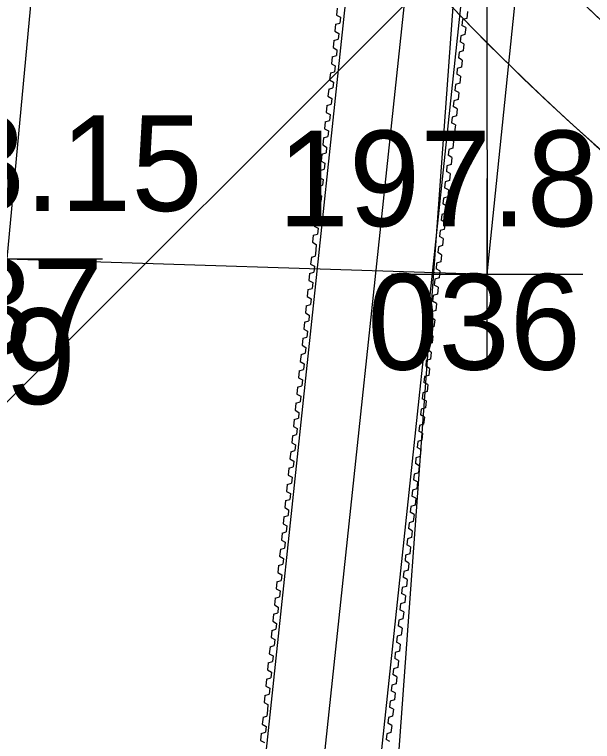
# Model space of a CAD drawing. Extents: x -706655 to -706193, y -1036183 to -1034979.
# Drawn here: x -706606.149 to -706603.13, y -1035105.504 to -1035101.703 of the extents above; entities that cross this region are included whole.
import ezdxf

# ---------------------------------------------------------------- set-up
doc = ezdxf.new("R2010")
doc.units = 0
for name, color, linetype in [('01', 7, 'Continuous'), ('křížky', 7, 'Continuous'), ('Nová vrstva (1)', 7, 'Continuous'), ('Nová vrstva (11)', 7, 'Continuous'), ('Nová vrstva (4)', 7, 'Continuous'), ('Stávající terén', 7, 'Continuous'), ('výšky', 7, 'Continuous'), ('čísla bodu', 7, 'Continuous')]:
    doc.layers.add(name, color=color, linetype=linetype)

msp = doc.modelspace()

# ---------------------------------------------------------------- linework, layer by layer
at = {"layer": '01'}
for p, q in [((-706604.0546, -1035098.1893), (-706605.8115, -1035114.7563)), ((-706603.4625, -1035098.2947), (-706605.2148, -1035114.8196)), ((-706604.4629, -1035101.6693), (-706604.4668, -1035101.7058)), ((-706604.4668, -1035101.7058), (-706604.4466, -1035101.717)), ((-706603.7829, -1035101.6865), (-706603.7868, -1035101.723)), ((-706604.4466, -1035101.717), (-706604.4498, -1035101.7474)), ((-706603.8088, -1035101.7298), (-706603.8121, -1035101.7601)), ((-706603.7868, -1035101.723), (-706603.8088, -1035101.7298)), ((-706604.4719, -1035101.7541), (-706604.4758, -1035101.7907)), ((-706604.4719, -1035101.7541), (-706604.4498, -1035101.7474)), ((-706603.7919, -1035101.7713), (-706603.8121, -1035101.7601)), ((-706603.7919, -1035101.7713), (-706603.7958, -1035101.8079)), ((-706604.4758, -1035101.7907), (-706604.4556, -1035101.8019)), ((-706604.4556, -1035101.8019), (-706604.4588, -1035101.8322)), ((-706603.8178, -1035101.8146), (-706603.8211, -1035101.845)), ((-706603.7958, -1035101.8079), (-706603.8178, -1035101.8146)), ((-706604.4809, -1035101.839), (-706604.4848, -1035101.8755)), ((-706604.4809, -1035101.839), (-706604.4588, -1035101.8322)), ((-706603.8009, -1035101.8562), (-706603.8211, -1035101.845)), ((-706603.8009, -1035101.8562), (-706603.8048, -1035101.8927)), ((-706604.4848, -1035101.8755), (-706604.4646, -1035101.8868)), ((-706604.4646, -1035101.8868), (-706604.4678, -1035101.9171)), ((-706603.8048, -1035101.8927), (-706603.8268, -1035101.8995)), ((-706604.4899, -1035101.9239), (-706604.4938, -1035101.9604)), ((-706604.4899, -1035101.9239), (-706604.4678, -1035101.9171)), ((-706603.8268, -1035101.8995), (-706603.8301, -1035101.9298)), ((-706603.8099, -1035101.9411), (-706603.8301, -1035101.9298)), ((-706604.4938, -1035101.9604), (-706604.4736, -1035101.9716)), ((-706604.4736, -1035101.9716), (-706604.4768, -1035102.002)), ((-706603.8099, -1035101.9411), (-706603.8138, -1035101.9776)), ((-706604.4989, -1035102.0087), (-706604.5028, -1035102.0453)), ((-706604.4989, -1035102.0087), (-706604.4768, -1035102.002)), ((-706603.8358, -1035101.9844), (-706603.8391, -1035102.0147)), ((-706603.8138, -1035101.9776), (-706603.8358, -1035101.9844)), ((-706604.5028, -1035102.0453), (-706604.4826, -1035102.0565)), ((-706603.8189, -1035102.0259), (-706603.8391, -1035102.0147)), ((-706603.8189, -1035102.0259), (-706603.8228, -1035102.0625)), ((-706604.5079, -1035102.0936), (-706604.4858, -1035102.0869)), ((-706604.4826, -1035102.0565), (-706604.4858, -1035102.0869)), ((-706603.8448, -1035102.0692), (-706603.8481, -1035102.0996)), ((-706603.8228, -1035102.0625), (-706603.8448, -1035102.0692)), ((-706604.5079, -1035102.0936), (-706604.5118, -1035102.1301)), ((-706603.8279, -1035102.1108), (-706603.8481, -1035102.0996)), ((-706603.8279, -1035102.1108), (-706603.8318, -1035102.1473)), ((-706604.5118, -1035102.1301), (-706604.4916, -1035102.1414)), ((-706604.4916, -1035102.1414), (-706604.4948, -1035102.1717)), ((-706603.8538, -1035102.1541), (-706603.8571, -1035102.1844)), ((-706603.8318, -1035102.1473), (-706603.8538, -1035102.1541)), ((-706604.5169, -1035102.1785), (-706604.5208, -1035102.215)), ((-706604.5169, -1035102.1785), (-706604.4948, -1035102.1717)), ((-706603.8369, -1035102.1957), (-706603.8571, -1035102.1844)), ((-706603.8369, -1035102.1957), (-706603.8408, -1035102.2322)), ((-706604.5208, -1035102.215), (-706604.5006, -1035102.2262)), ((-706604.5006, -1035102.2262), (-706604.5038, -1035102.2566)), ((-706603.8628, -1035102.239), (-706603.8661, -1035102.2693)), ((-706603.8408, -1035102.2322), (-706603.8628, -1035102.239)), ((-706604.5259, -1035102.2633), (-706604.5298, -1035102.2999)), ((-706604.5259, -1035102.2633), (-706604.5038, -1035102.2566)), ((-706603.8459, -1035102.2805), (-706603.8661, -1035102.2693)), ((-706604.5298, -1035102.2999), (-706604.5096, -1035102.3111)), ((-706604.5096, -1035102.3111), (-706604.5128, -1035102.3415)), ((-706603.8498, -1035102.3171), (-706603.8718, -1035102.3238)), ((-706603.8459, -1035102.2805), (-706603.8498, -1035102.3171)), ((-706604.5349, -1035102.3482), (-706604.5388, -1035102.3847)), ((-706604.5349, -1035102.3482), (-706604.5128, -1035102.3415)), ((-706603.8718, -1035102.3238), (-706603.8751, -1035102.3542)), ((-706603.8549, -1035102.3654), (-706603.8751, -1035102.3542)), ((-706604.5388, -1035102.3847), (-706604.5186, -1035102.396)), ((-706603.8549, -1035102.3654), (-706603.8588, -1035102.4019)), ((-706604.5439, -1035102.4331), (-706604.5218, -1035102.4263)), ((-706604.5186, -1035102.396), (-706604.5218, -1035102.4263)), ((-706603.8808, -1035102.4087), (-706603.8841, -1035102.439)), ((-706603.8588, -1035102.4019), (-706603.8808, -1035102.4087)), ((-706604.5439, -1035102.4331), (-706604.5478, -1035102.4696)), ((-706603.8639, -1035102.4503), (-706603.8841, -1035102.439)), ((-706603.8639, -1035102.4503), (-706603.8678, -1035102.4868)), ((-706604.5478, -1035102.4696), (-706604.5276, -1035102.4808)), ((-706604.5276, -1035102.4808), (-706604.5308, -1035102.5112)), ((-706603.8898, -1035102.4936), (-706603.8931, -1035102.5239)), ((-706603.8678, -1035102.4868), (-706603.8898, -1035102.4936)), ((-706604.5529, -1035102.5179), (-706604.5568, -1035102.5545)), ((-706604.5529, -1035102.5179), (-706604.5308, -1035102.5112)), ((-706603.8729, -1035102.5351), (-706603.8931, -1035102.5239)), ((-706603.8729, -1035102.5351), (-706603.8768, -1035102.5717)), ((-706604.5568, -1035102.5545), (-706604.5366, -1035102.5657)), ((-706604.5366, -1035102.5657), (-706604.5398, -1035102.5961)), ((-706603.8988, -1035102.5784), (-706603.9021, -1035102.6088)), ((-706603.8768, -1035102.5717), (-706603.8988, -1035102.5784)), ((-706604.5619, -1035102.6028), (-706604.5658, -1035102.6393)), ((-706604.5619, -1035102.6028), (-706604.5398, -1035102.5961)), ((-706603.8819, -1035102.62), (-706603.9021, -1035102.6088)), ((-706603.8819, -1035102.62), (-706603.8858, -1035102.6565)), ((-706604.5658, -1035102.6393), (-706604.5456, -1035102.6506)), ((-706604.5456, -1035102.6506), (-706604.5488, -1035102.6809)), ((-706603.8858, -1035102.6565), (-706603.9078, -1035102.6633)), ((-706604.5709, -1035102.6877), (-706604.5748, -1035102.7242)), ((-706604.5709, -1035102.6877), (-706604.5488, -1035102.6809)), ((-706603.9078, -1035102.6633), (-706603.9111, -1035102.6936)), ((-706603.8909, -1035102.7049), (-706603.9111, -1035102.6936)), ((-706604.5748, -1035102.7242), (-706604.5546, -1035102.7354)), ((-706604.5546, -1035102.7354), (-706604.5578, -1035102.7658)), ((-706603.8909, -1035102.7049), (-706603.8948, -1035102.7414)), ((-706604.5799, -1035102.7725), (-706604.5838, -1035102.8091)), ((-706604.5799, -1035102.7725), (-706604.5578, -1035102.7658)), ((-706603.9168, -1035102.7482), (-706603.9201, -1035102.7785)), ((-706603.8948, -1035102.7414), (-706603.9168, -1035102.7482)), ((-706604.5838, -1035102.8091), (-706604.5636, -1035102.8203)), ((-706603.8999, -1035102.7897), (-706603.9201, -1035102.7785)), ((-706603.8999, -1035102.7897), (-706603.9038, -1035102.8263)), ((-706604.5636, -1035102.8203), (-706604.5668, -1035102.8507)), ((-706603.9258, -1035102.833), (-706603.9291, -1035102.8634)), ((-706603.9038, -1035102.8263), (-706603.9258, -1035102.833)), ((-706604.5889, -1035102.8574), (-706604.5928, -1035102.8939)), ((-706604.5889, -1035102.8574), (-706604.5668, -1035102.8507)), ((-706603.9089, -1035102.8746), (-706603.9291, -1035102.8634)), ((-706603.9089, -1035102.8746), (-706603.9128, -1035102.9111)), ((-706604.5928, -1035102.8939), (-706604.5726, -1035102.9052)), ((-706604.5726, -1035102.9052), (-706604.5758, -1035102.9355)), ((-706603.9348, -1035102.9179), (-706603.9381, -1035102.9482)), ((-706603.9128, -1035102.9111), (-706603.9348, -1035102.9179)), ((-706604.5758, -1035102.9355), (-706604.579, -1035102.9659)), ((-706603.9179, -1035102.9595), (-706603.9381, -1035102.9482)), ((-706603.9179, -1035102.9595), (-706603.9218, -1035102.996)), ((-706604.5984, -1035102.9718), (-706604.6023, -1035103.0083)), ((-706604.5984, -1035102.9718), (-706604.579, -1035102.9659)), ((-706603.9218, -1035102.9958), (-706603.9438, -1035103.0025)), ((-706603.9218, -1035102.996), (-706603.9438, -1035103.0028)), ((-706604.6023, -1035103.0083), (-706604.5822, -1035103.0196)), ((-706604.5822, -1035103.0196), (-706604.5854, -1035103.0499)), ((-706603.9438, -1035103.0025), (-706603.947, -1035103.0329)), ((-706603.9269, -1035103.0441), (-706603.947, -1035103.0329)), ((-706604.6074, -1035103.0567), (-706604.6113, -1035103.0932)), ((-706604.6074, -1035103.0567), (-706604.5854, -1035103.0499)), ((-706603.9269, -1035103.0441), (-706603.9308, -1035103.0807)), ((-706604.6113, -1035103.0932), (-706604.5912, -1035103.1044)), ((-706604.5912, -1035103.1044), (-706604.5944, -1035103.1348)), ((-706603.9528, -1035103.0874), (-706603.956, -1035103.1178)), ((-706603.9308, -1035103.0807), (-706603.9528, -1035103.0874)), ((-706604.6164, -1035103.1415), (-706604.6203, -1035103.1781)), ((-706604.6164, -1035103.1415), (-706604.5944, -1035103.1348)), ((-706603.9359, -1035103.129), (-706603.956, -1035103.1178)), ((-706603.9359, -1035103.129), (-706603.9398, -1035103.1655)), ((-706604.6203, -1035103.1781), (-706604.6002, -1035103.1893)), ((-706604.6002, -1035103.1893), (-706604.6034, -1035103.2197)), ((-706603.9618, -1035103.1723), (-706603.965, -1035103.2026)), ((-706603.9398, -1035103.1655), (-706603.9618, -1035103.1723)), ((-706604.6254, -1035103.2264), (-706604.6293, -1035103.2629)), ((-706604.6254, -1035103.2264), (-706604.6034, -1035103.2197)), ((-706603.9449, -1035103.2139), (-706603.965, -1035103.2026)), ((-706603.9449, -1035103.2139), (-706603.9488, -1035103.2504)), ((-706604.6293, -1035103.2629), (-706604.6092, -1035103.2742)), ((-706603.9708, -1035103.2571), (-706603.974, -1035103.2875)), ((-706603.9488, -1035103.2504), (-706603.9708, -1035103.2571)), ((-706604.6344, -1035103.3113), (-706604.6124, -1035103.3045)), ((-706604.6092, -1035103.2742), (-706604.6124, -1035103.3045)), ((-706603.9539, -1035103.2987), (-706603.974, -1035103.2875)), ((-706603.9539, -1035103.2987), (-706603.9578, -1035103.3353)), ((-706604.6344, -1035103.3113), (-706604.6383, -1035103.3478)), ((-706603.9798, -1035103.342), (-706603.983, -1035103.3724)), ((-706603.9578, -1035103.3353), (-706603.9798, -1035103.342)), ((-706604.6383, -1035103.3478), (-706604.6182, -1035103.359)), ((-706604.6182, -1035103.359), (-706604.6214, -1035103.3894)), ((-706603.9629, -1035103.3836), (-706603.983, -1035103.3724)), ((-706604.6434, -1035103.3961), (-706604.6473, -1035103.4327)), ((-706604.6434, -1035103.3961), (-706604.6214, -1035103.3894)), ((-706603.9629, -1035103.3836), (-706603.9668, -1035103.4201)), ((-706604.6473, -1035103.4327), (-706604.6272, -1035103.4439)), ((-706604.6272, -1035103.4439), (-706604.6304, -1035103.4743)), ((-706603.9888, -1035103.4269), (-706603.992, -1035103.4572)), ((-706603.9719, -1035103.4685), (-706603.992, -1035103.4572)), ((-706603.9668, -1035103.4201), (-706603.9888, -1035103.4269)), ((-706604.6524, -1035103.481), (-706604.6563, -1035103.5175)), ((-706604.6524, -1035103.481), (-706604.6304, -1035103.4743)), ((-706603.9719, -1035103.4685), (-706603.9758, -1035103.505)), ((-706604.6563, -1035103.5175), (-706604.6362, -1035103.5288)), ((-706604.6362, -1035103.5288), (-706604.6394, -1035103.5591)), ((-706603.9978, -1035103.5117), (-706604.001, -1035103.5421)), ((-706603.9758, -1035103.505), (-706603.9978, -1035103.5117)), ((-706604.6614, -1035103.5659), (-706604.6653, -1035103.6024)), ((-706604.6614, -1035103.5659), (-706604.6394, -1035103.5591)), ((-706603.9809, -1035103.5533), (-706604.001, -1035103.5421)), ((-706603.9809, -1035103.5533), (-706603.9848, -1035103.5899)), ((-706604.6653, -1035103.6024), (-706604.6452, -1035103.6136)), ((-706604.0068, -1035103.5966), (-706604.01, -1035103.627)), ((-706603.9848, -1035103.5899), (-706604.0068, -1035103.5966)), ((-706604.6704, -1035103.6507), (-706604.6484, -1035103.644)), ((-706604.6452, -1035103.6136), (-706604.6484, -1035103.644)), ((-706603.9899, -1035103.6382), (-706604.01, -1035103.627)), ((-706603.9899, -1035103.6382), (-706603.9938, -1035103.6747)), ((-706604.6704, -1035103.6507), (-706604.6743, -1035103.6873)), ((-706604.0158, -1035103.6815), (-706604.019, -1035103.7118)), ((-706603.9938, -1035103.6747), (-706604.0158, -1035103.6815)), ((-706604.6743, -1035103.6873), (-706604.6542, -1035103.6985)), ((-706604.6542, -1035103.6985), (-706604.6574, -1035103.7289)), ((-706603.9989, -1035103.7231), (-706604.019, -1035103.7118)), ((-706603.9989, -1035103.7231), (-706604.0028, -1035103.7596)), ((-706604.6794, -1035103.7356), (-706604.6833, -1035103.7721)), ((-706604.6794, -1035103.7356), (-706604.6574, -1035103.7289)), ((-706604.0028, -1035103.7596), (-706604.0248, -1035103.7663)), ((-706604.6833, -1035103.7721), (-706604.6632, -1035103.7834)), ((-706604.6632, -1035103.7834), (-706604.6664, -1035103.8137)), ((-706604.0248, -1035103.7663), (-706604.028, -1035103.7967)), ((-706604.0079, -1035103.8079), (-706604.028, -1035103.7967)), ((-706604.6884, -1035103.8205), (-706604.6923, -1035103.857)), ((-706604.6884, -1035103.8205), (-706604.6664, -1035103.8137)), ((-706604.0079, -1035103.8079), (-706604.0118, -1035103.8445)), ((-706604.6923, -1035103.857), (-706604.6722, -1035103.8682)), ((-706604.6722, -1035103.8682), (-706604.6754, -1035103.8986)), ((-706604.0338, -1035103.8512), (-706604.037, -1035103.8816)), ((-706604.0118, -1035103.8445), (-706604.0338, -1035103.8512)), ((-706604.6974, -1035103.9053), (-706604.7013, -1035103.9419)), ((-706604.6974, -1035103.9053), (-706604.6754, -1035103.8986)), ((-706604.0169, -1035103.8928), (-706604.037, -1035103.8816)), ((-706604.0169, -1035103.8928), (-706604.0208, -1035103.9293)), ((-706604.7013, -1035103.9419), (-706604.6812, -1035103.9531)), ((-706604.0428, -1035103.9361), (-706604.046, -1035103.9664)), ((-706604.0208, -1035103.9293), (-706604.0428, -1035103.9361)), ((-706604.7064, -1035103.9902), (-706604.6844, -1035103.9835)), ((-706604.6812, -1035103.9531), (-706604.6844, -1035103.9835)), ((-706604.0259, -1035103.9777), (-706604.046, -1035103.9664)), ((-706604.0259, -1035103.9777), (-706604.0298, -1035104.0142)), ((-706604.7064, -1035103.9902), (-706604.7103, -1035104.0267)), ((-706604.7103, -1035104.0267), (-706604.6902, -1035104.038)), ((-706604.0518, -1035104.0209), (-706604.055, -1035104.0513)), ((-706604.0298, -1035104.0142), (-706604.0518, -1035104.0209)), ((-706604.6902, -1035104.038), (-706604.6934, -1035104.0683)), ((-706604.0349, -1035104.0625), (-706604.055, -1035104.0513)), ((-706604.0349, -1035104.0625), (-706604.0388, -1035104.0991)), ((-706604.7154, -1035104.0751), (-706604.7193, -1035104.1116)), ((-706604.7154, -1035104.0751), (-706604.6934, -1035104.0683)), ((-706604.0388, -1035104.0991), (-706604.0608, -1035104.1058)), ((-706604.7193, -1035104.1116), (-706604.6992, -1035104.1228)), ((-706604.6992, -1035104.1228), (-706604.7024, -1035104.1532)), ((-706604.0608, -1035104.1058), (-706604.064, -1035104.1362)), ((-706604.0439, -1035104.1474), (-706604.064, -1035104.1362)), ((-706604.7244, -1035104.1599), (-706604.7283, -1035104.1965)), ((-706604.7244, -1035104.1599), (-706604.7024, -1035104.1532)), ((-706604.0439, -1035104.1474), (-706604.0478, -1035104.1839)), ((-706604.7283, -1035104.1965), (-706604.7082, -1035104.2077)), ((-706604.7082, -1035104.2077), (-706604.7114, -1035104.2381)), ((-706604.0698, -1035104.1907), (-706604.073, -1035104.221)), ((-706604.0478, -1035104.1839), (-706604.0698, -1035104.1907)), ((-706604.7334, -1035104.2448), (-706604.7373, -1035104.2813)), ((-706604.7334, -1035104.2448), (-706604.7114, -1035104.2381)), ((-706604.0529, -1035104.2323), (-706604.073, -1035104.221)), ((-706604.0529, -1035104.2323), (-706604.0568, -1035104.2688)), ((-706604.7373, -1035104.2813), (-706604.7172, -1035104.2926)), ((-706604.7172, -1035104.2926), (-706604.7204, -1035104.3229)), ((-706604.0788, -1035104.2755), (-706604.082, -1035104.3059)), ((-706604.0568, -1035104.2688), (-706604.0788, -1035104.2755)), ((-706604.7424, -1035104.3297), (-706604.7463, -1035104.3662)), ((-706604.7424, -1035104.3297), (-706604.7204, -1035104.3229)), ((-706604.0619, -1035104.3171), (-706604.082, -1035104.3059)), ((-706604.0619, -1035104.3171), (-706604.0658, -1035104.3537)), ((-706604.7463, -1035104.3662), (-706604.7262, -1035104.3774)), ((-706604.0878, -1035104.3604), (-706604.091, -1035104.3908)), ((-706604.0658, -1035104.3537), (-706604.0878, -1035104.3604)), ((-706604.7514, -1035104.4145), (-706604.7294, -1035104.4078)), ((-706604.7262, -1035104.3774), (-706604.7294, -1035104.4078)), ((-706604.0709, -1035104.402), (-706604.091, -1035104.3908)), ((-706604.0709, -1035104.402), (-706604.0747, -1035104.4385)), ((-706604.7514, -1035104.4145), (-706604.7553, -1035104.4511)), ((-706604.0968, -1035104.4453), (-706604.1, -1035104.4756)), ((-706604.0747, -1035104.4385), (-706604.0968, -1035104.4453)), ((-706604.7553, -1035104.4511), (-706604.7352, -1035104.4623)), ((-706604.7352, -1035104.4623), (-706604.7384, -1035104.4927)), ((-706604.0799, -1035104.4869), (-706604.1, -1035104.4756)), ((-706604.7604, -1035104.4994), (-706604.7643, -1035104.5359)), ((-706604.7604, -1035104.4994), (-706604.7384, -1035104.4927)), ((-706604.0799, -1035104.4869), (-706604.0837, -1035104.5234)), ((-706604.7643, -1035104.5359), (-706604.7442, -1035104.5472)), ((-706604.7442, -1035104.5472), (-706604.7474, -1035104.5775)), ((-706604.1058, -1035104.5301), (-706604.109, -1035104.5605)), ((-706604.0837, -1035104.5234), (-706604.1058, -1035104.5301)), ((-706604.7694, -1035104.5843), (-706604.7733, -1035104.6208)), ((-706604.7694, -1035104.5843), (-706604.7474, -1035104.5775)), ((-706604.0889, -1035104.5717), (-706604.109, -1035104.5605)), ((-706604.0889, -1035104.5717), (-706604.0927, -1035104.6083)), ((-706604.7733, -1035104.6208), (-706604.7532, -1035104.632)), ((-706604.7532, -1035104.632), (-706604.7564, -1035104.6624)), ((-706604.1148, -1035104.615), (-706604.118, -1035104.6454)), ((-706604.0927, -1035104.6083), (-706604.1148, -1035104.615)), ((-706604.7784, -1035104.6691), (-706604.7823, -1035104.7057)), ((-706604.7784, -1035104.6691), (-706604.7564, -1035104.6624)), ((-706604.0979, -1035104.6566), (-706604.118, -1035104.6454)), ((-706604.0979, -1035104.6566), (-706604.1017, -1035104.6931)), ((-706604.7823, -1035104.7057), (-706604.7622, -1035104.7169)), ((-706604.1238, -1035104.6999), (-706604.127, -1035104.7302)), ((-706604.1017, -1035104.6931), (-706604.1238, -1035104.6999)), ((-706604.7874, -1035104.754), (-706604.7654, -1035104.7473)), ((-706604.7622, -1035104.7169), (-706604.7654, -1035104.7473)), ((-706604.1069, -1035104.7415), (-706604.127, -1035104.7302)), ((-706604.1069, -1035104.7415), (-706604.1107, -1035104.778)), ((-706604.7874, -1035104.754), (-706604.7913, -1035104.7905)), ((-706604.1328, -1035104.7847), (-706604.136, -1035104.8151)), ((-706604.1107, -1035104.778), (-706604.1328, -1035104.7847)), ((-706604.7913, -1035104.7905), (-706604.7712, -1035104.8018)), ((-706604.7712, -1035104.8018), (-706604.7744, -1035104.8321)), ((-706604.1159, -1035104.8263), (-706604.136, -1035104.8151)), ((-706604.7964, -1035104.8389), (-706604.8003, -1035104.8754)), ((-706604.7964, -1035104.8389), (-706604.7744, -1035104.8321)), ((-706604.1197, -1035104.8627), (-706604.1418, -1035104.8694)), ((-706604.1197, -1035104.8629), (-706604.1418, -1035104.8696)), ((-706604.1159, -1035104.8263), (-706604.1197, -1035104.8629)), ((-706604.8003, -1035104.8754), (-706604.7802, -1035104.8866)), ((-706604.7802, -1035104.8866), (-706604.7834, -1035104.917)), ((-706604.1418, -1035104.8694), (-706604.145, -1035104.8998)), ((-706604.1248, -1035104.911), (-706604.145, -1035104.8998)), ((-706604.8054, -1035104.9237), (-706604.8093, -1035104.9603)), ((-706604.8054, -1035104.9237), (-706604.7834, -1035104.917)), ((-706604.1248, -1035104.911), (-706604.1287, -1035104.9475)), ((-706604.8093, -1035104.9603), (-706604.7892, -1035104.9715)), ((-706604.7892, -1035104.9715), (-706604.7924, -1035105.0019)), ((-706604.1508, -1035104.9543), (-706604.154, -1035104.9846)), ((-706604.1287, -1035104.9475), (-706604.1508, -1035104.9543)), ((-706604.8144, -1035105.0086), (-706604.8183, -1035105.0451)), ((-706604.8144, -1035105.0086), (-706604.7924, -1035105.0019)), ((-706604.1338, -1035104.9959), (-706604.154, -1035104.9846)), ((-706604.1338, -1035104.9959), (-706604.1377, -1035105.0324)), ((-706604.8183, -1035105.0451), (-706604.7982, -1035105.0564)), ((-706604.1598, -1035105.0391), (-706604.163, -1035105.0695)), ((-706604.1377, -1035105.0324), (-706604.1598, -1035105.0391)), ((-706604.8234, -1035105.0935), (-706604.8014, -1035105.0867)), ((-706604.7982, -1035105.0564), (-706604.8014, -1035105.0867)), ((-706604.1428, -1035105.0807), (-706604.163, -1035105.0695)), ((-706604.1428, -1035105.0807), (-706604.1467, -1035105.1173)), ((-706604.8234, -1035105.0935), (-706604.8273, -1035105.13)), ((-706604.8273, -1035105.13), (-706604.8072, -1035105.1412)), ((-706604.1688, -1035105.124), (-706604.172, -1035105.1544)), ((-706604.1467, -1035105.1173), (-706604.1688, -1035105.124)), ((-706604.8072, -1035105.1412), (-706604.8104, -1035105.1716)), ((-706604.1518, -1035105.1656), (-706604.172, -1035105.1544)), ((-706604.1518, -1035105.1656), (-706604.1557, -1035105.2021)), ((-706604.8324, -1035105.1783), (-706604.8363, -1035105.2149)), ((-706604.8324, -1035105.1783), (-706604.8104, -1035105.1716)), ((-706604.1557, -1035105.2021), (-706604.1778, -1035105.2089)), ((-706604.8363, -1035105.2149), (-706604.8162, -1035105.2261)), ((-706604.8162, -1035105.2261), (-706604.8194, -1035105.2565)), ((-706604.1778, -1035105.2089), (-706604.181, -1035105.2392)), ((-706604.1608, -1035105.2505), (-706604.181, -1035105.2392)), ((-706604.8414, -1035105.2632), (-706604.8453, -1035105.2997)), ((-706604.8414, -1035105.2632), (-706604.8194, -1035105.2565)), ((-706604.1608, -1035105.2505), (-706604.1647, -1035105.287)), ((-706604.8453, -1035105.2997), (-706604.8252, -1035105.311)), ((-706604.8252, -1035105.311), (-706604.8284, -1035105.3413)), ((-706604.1868, -1035105.2937), (-706604.19, -1035105.3241)), ((-706604.1647, -1035105.287), (-706604.1868, -1035105.2937)), ((-706604.8284, -1035105.3413), (-706604.8316, -1035105.3717)), ((-706604.1698, -1035105.3353), (-706604.19, -1035105.3241)), ((-706604.1698, -1035105.3353), (-706604.1737, -1035105.3719)), ((-706604.851, -1035105.3776), (-706604.8549, -1035105.4141)), ((-706604.851, -1035105.3776), (-706604.8316, -1035105.3717)), ((-706604.1958, -1035105.3786), (-706604.199, -1035105.409)), ((-706604.1737, -1035105.3719), (-706604.1958, -1035105.3786)), ((-706604.8549, -1035105.4141), (-706604.8347, -1035105.4254)), ((-706604.8347, -1035105.4254), (-706604.8379, -1035105.4557)), ((-706604.1788, -1035105.4202), (-706604.199, -1035105.409)), ((-706604.1788, -1035105.4202), (-706604.1827, -1035105.4567)), ((-706604.86, -1035105.4625), (-706604.8639, -1035105.499)), ((-706604.86, -1035105.4625), (-706604.8379, -1035105.4557)), ((-706604.2048, -1035105.4635), (-706604.208, -1035105.4938)), ((-706604.1827, -1035105.4567), (-706604.2048, -1035105.4635)), ((-706604.8639, -1035105.499), (-706604.8437, -1035105.5102)), ((-706604.1878, -1035105.5051), (-706604.208, -1035105.4938))]:
    msp.add_line(p, q, dxfattribs=at)
at = {"layer": 'křížky'}
for p, q in [((-706603.68, -1035103.56), (-706603.68, -1035102.56)), ((-706606.69, -1035102.98), (-706605.69, -1035102.98)), ((-706604.18, -1035103.06), (-706603.18, -1035103.06)), ((-706603.68, -1035103.06), (-706603.68, -1035103.06))]:
    msp.add_line(p, q, dxfattribs=at)
at = {"layer": 'Nová vrstva (1)'}
for centre, radius, start, end in [((-706594.467, -1035092.6797), 12.5, 202.2283, 260.54711), ((-706594.4671, -1035092.6792), 12.5, 202.22971, 231.15045), ((-706594.467, -1035092.6797), 13, 206.08714, 260.54711), ((-706594.4671, -1035092.6792), 13, 206.08855, 231.15045)]:
    msp.add_arc(centre, radius, start, end, dxfattribs=at)
at = {"layer": 'Nová vrstva (11)'}
msp.add_line((-706603.7007, -1035097.7641), (-706605.7696, -1035117.2094), dxfattribs=at)
at = {"layer": 'Nová vrstva (4)'}
for p, q in [((-706595.5132, -1034986.9872), (-706604.2289, -1035106.7382)), ((-706608.3912, -1035105.9312), (-706603.8388, -1035101.3789))]:
    msp.add_line(p, q, dxfattribs=at)
at = {"layer": 'Stávající terén'}
for points in [[(-706603.54, -1035076.59), (-706604.73, -1035087.33), (-706606.19, -1035102.98), (-706603.68, -1035103.06)], [(-706602.34, -1035076.61), (-706603.7, -1035087.44), (-706603.68, -1035103.06)], [(-706603.68, -1035103.06), (-706602.08, -1035087.49), (-706601.32, -1035076.76)]]:
    msp.add_lwpolyline(points, dxfattribs=at)
at = {"layer": 'čísla bodu'}
for p, q in [((-706603.68, -1035103.56), (-706603.68, -1035102.56)), ((-706606.69, -1035102.98), (-706605.69, -1035102.98)), ((-706604.18, -1035103.06), (-706603.18, -1035103.06)), ((-706603.68, -1035103.06), (-706603.68, -1035103.06))]:
    msp.add_line(p, q, dxfattribs=at)

# ---------------------------------------------------------------- texts
at = {"layer": 'výšky'}
for s, p in [('198.15', (-706607.212, -1035102.73)), ('197.89', (-706604.774, -1035102.81)), ('198.19', (-706607.874, -1035103.74))]:
    msp.add_text(s, height=0.5, dxfattribs=at).set_placement(p)
at = {"layer": 'čísla bodu'}
for s, p in [('037', (-706606.802, -1035103.48)), ('036', (-706604.306, -1035103.56))]:
    msp.add_text(s, height=0.5, dxfattribs=at).set_placement(p)

doc.saveas('drawing.dxf')
